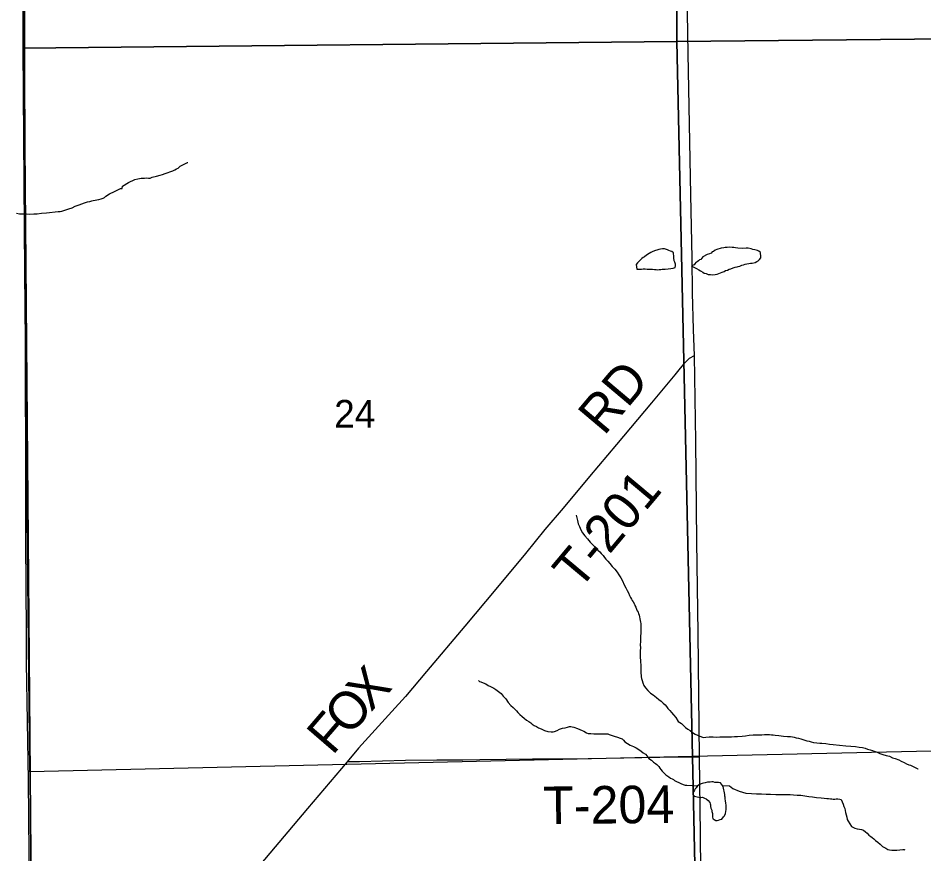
# Model space of a CAD drawing. Extents: x 10.6 to 44.6, y -2.6 to 23.4.
# Drawn here: x 15.273 to 16.643, y 16.432 to 17.696 of the extents above; entities that cross this region are included whole.
import ezdxf

# ---------------------------------------------------------------- set-up
doc = ezdxf.new("R2010")
doc.units = 0
for name, color, linetype in [('GM_X_County_Road', 7, 'Continuous'), ('GM_X_Minor_Lake', 7, 'Continuous'), ('GM_X_Minor_River', 7, 'Continuous'), ('GM_X_Section', 7, 'Continuous'), ('GM_X_Section_Text', 7, 'Continuous'), ('GM_X_Township', 7, 'Continuous'), ('GM_X_Township_Road', 7, 'Continuous'), ('GM_X_Township_Road_Text', 7, 'Continuous')]:
    doc.layers.add(name, color=color, linetype=linetype)

msp = doc.modelspace()

# ---------------------------------------------------------------- linework, layer by layer
at = {"layer": 'GM_X_County_Road'}
msp.add_lwpolyline([(16.2763, 18.1986), (16.2775, 18.1572), (16.2791, 18.0677), (16.2823, 17.8579), (16.286, 17.6424), (16.2902, 17.4286), (16.292, 17.333), (16.2926, 17.2804), (16.2943, 17.2251), (16.2954, 17.1849), (16.2974, 17.0561), (16.299, 16.9044), (16.301, 16.7657), (16.303, 16.5782), (16.3046, 16.4615), (16.3053, 16.4059), (16.3064, 16.3215), (16.308, 16.2088), (16.3086, 16.1439), (16.3111, 15.9738), (16.3131, 15.7931), (16.3156, 15.6219), (16.3166, 15.5267)], dxfattribs=at)
at = {"layer": 'GM_X_Minor_Lake'}
for points in [[(16.2654, 17.3297), (16.2647, 17.3323), (16.2646, 17.335), (16.2646, 17.3369), (16.2642, 17.3388), (16.2641, 17.3407), (16.2618, 17.3429), (16.2599, 17.3436), (16.2572, 17.3447), (16.2553, 17.3454), (16.2507, 17.3469), (16.2476, 17.3472), (16.2446, 17.3467), (16.2419, 17.3459), (16.2389, 17.3451), (16.237, 17.3443), (16.2332, 17.343), (16.2302, 17.3414), (16.2276, 17.3399), (16.2235, 17.3375), (16.2205, 17.3351), (16.2182, 17.3339), (16.2164, 17.3324), (16.2145, 17.3304), (16.2115, 17.3273), (16.2097, 17.3258), (16.2078, 17.3234), (16.2087, 17.3162)], [(16.3965, 17.3352), (16.3966, 17.3369), (16.3962, 17.3395), (16.3958, 17.3414), (16.3934, 17.3433), (16.3915, 17.3444), (16.3892, 17.3451), (16.3873, 17.3454), (16.3846, 17.3461), (16.3816, 17.3468), (16.3773, 17.3478), (16.3743, 17.3478), (16.369, 17.3476), (16.3617, 17.3479), (16.3583, 17.3485), (16.3556, 17.3489), (16.3533, 17.3492), (16.3492, 17.3495), (16.3454, 17.349), (16.3427, 17.349), (16.3404, 17.3485), (16.3366, 17.3481), (16.3298, 17.346), (16.3272, 17.3448), (16.3249, 17.3432), (16.3227, 17.3424), (16.3212, 17.3405), (16.3189, 17.3393), (16.3152, 17.3384), (16.3088, 17.3349), (16.3058, 17.331), (16.3039, 17.3302), (16.3021, 17.329), (16.3002, 17.3271), (16.2983, 17.3263), (16.2965, 17.3243), (16.2954, 17.3228)], [(16.2087, 17.3162), (16.2091, 17.3162), (16.2095, 17.3162), (16.2114, 17.3163), (16.2137, 17.3163), (16.216, 17.3164), (16.2186, 17.3165), (16.2213, 17.3165), (16.2247, 17.3162), (16.227, 17.3163), (16.2293, 17.3163), (16.2327, 17.316), (16.2354, 17.3157), (16.2381, 17.3158), (16.2403, 17.3154), (16.2426, 17.3155), (16.2449, 17.3155), (16.2472, 17.316), (16.2491, 17.316), (16.2517, 17.3161), (16.2563, 17.3165), (16.2605, 17.317), (16.2639, 17.3179), (16.2669, 17.3187), (16.2672, 17.3214), (16.2672, 17.324), (16.2663, 17.3267), (16.2655, 17.3289), (16.2654, 17.3297)], [(16.2954, 17.3228), (16.2916, 17.3212), (16.2931, 17.3204), (16.2962, 17.3186), (16.2989, 17.3171), (16.3024, 17.3153), (16.3054, 17.3139), (16.3085, 17.3116), (16.3109, 17.3102), (16.3139, 17.3095), (16.317, 17.3084), (16.3204, 17.3081), (16.3239, 17.3078), (16.3273, 17.3083), (16.3303, 17.3087), (16.3329, 17.3095), (16.3356, 17.3107), (16.3382, 17.3119), (16.3409, 17.3128), (16.3431, 17.314), (16.3458, 17.3148), (16.3484, 17.316), (16.351, 17.3168), (16.3548, 17.318), (16.3578, 17.3192), (16.3605, 17.3197), (16.3624, 17.3205), (16.3646, 17.3209), (16.3677, 17.3221), (16.3703, 17.3229), (16.373, 17.3238), (16.3809, 17.3255), (16.3832, 17.3255), (16.3877, 17.3264), (16.3904, 17.3276), (16.3922, 17.3288), (16.3945, 17.3307), (16.3963, 17.3334), (16.3965, 17.3352)], [(16.3352, 16.5393), (16.3348, 16.5393), (16.3322, 16.5396), (16.3288, 16.5396), (16.3268, 16.5399), (16.3245, 16.5406), (16.3223, 16.5409), (16.32, 16.5405), (16.3177, 16.5405), (16.3158, 16.5404), (16.3124, 16.5392), (16.3097, 16.5388), (16.3079, 16.5383), (16.306, 16.5379), (16.3033, 16.5363), (16.3007, 16.5347), (16.2985, 16.532), (16.297, 16.5301), (16.2959, 16.5282), (16.2945, 16.5255), (16.2941, 16.5236), (16.2942, 16.5213), (16.2961, 16.519), (16.2999, 16.518), (16.3026, 16.5177), (16.3057, 16.5173), (16.3083, 16.5174), (16.3114, 16.5163), (16.3137, 16.5149), (16.3168, 16.5127), (16.3195, 16.5097), (16.32, 16.5078), (16.3204, 16.5059)], [(16.3352, 16.5393), (16.3348, 16.5393), (16.3322, 16.5396), (16.3288, 16.5396), (16.3268, 16.5399), (16.3245, 16.5406), (16.3223, 16.5409), (16.32, 16.5405), (16.3177, 16.5405), (16.3158, 16.5404), (16.3124, 16.5392), (16.3097, 16.5388), (16.3079, 16.5383), (16.306, 16.5379), (16.3033, 16.5363), (16.3007, 16.5347), (16.2985, 16.532), (16.297, 16.5301), (16.2959, 16.5282), (16.2945, 16.5255), (16.2941, 16.5236), (16.2942, 16.5213), (16.2961, 16.519), (16.2999, 16.518), (16.3026, 16.5177), (16.3057, 16.5173), (16.3083, 16.5174), (16.3114, 16.5163), (16.3137, 16.5149), (16.3168, 16.5127), (16.3195, 16.5097), (16.32, 16.5078), (16.3204, 16.5059), (16.3204, 16.5036), (16.3209, 16.501), (16.3221, 16.4979), (16.3221, 16.496), (16.3233, 16.493), (16.3234, 16.4907), (16.3235, 16.4881), (16.3239, 16.485), (16.3258, 16.4839), (16.3285, 16.4825), (16.3304, 16.4825), (16.3323, 16.4829), (16.335, 16.4838), (16.3372, 16.4842), (16.3398, 16.4877), (16.3417, 16.4896), (16.3428, 16.4931), (16.3434, 16.4961), (16.3438, 16.4988), (16.3441, 16.5019), (16.344, 16.5057), (16.3435, 16.5087), (16.3431, 16.5121), (16.3426, 16.5151), (16.3426, 16.5174), (16.3422, 16.5193), (16.3421, 16.5216), (16.3413, 16.5242), (16.3408, 16.5269), (16.3404, 16.5288), (16.3395, 16.5337), (16.3384, 16.5352), (16.3352, 16.5393)], [(16.3204, 16.5059), (16.3204, 16.5036), (16.3209, 16.501), (16.3221, 16.4979), (16.3221, 16.496), (16.3233, 16.493), (16.3234, 16.4907), (16.3235, 16.4881), (16.3239, 16.485), (16.3258, 16.4839), (16.3285, 16.4825), (16.3304, 16.4825), (16.3323, 16.4829), (16.335, 16.4838), (16.3372, 16.4842), (16.3398, 16.4877), (16.3417, 16.4896), (16.3428, 16.4931), (16.3434, 16.4961), (16.3438, 16.4988), (16.3441, 16.5019), (16.344, 16.5057), (16.3435, 16.5087), (16.3431, 16.5121), (16.3426, 16.5151), (16.3426, 16.5174), (16.3422, 16.5193), (16.3421, 16.5216), (16.3413, 16.5242), (16.3408, 16.5269), (16.3404, 16.5288), (16.3395, 16.5337), (16.3384, 16.5352), (16.3352, 16.5393)]]:
    msp.add_lwpolyline(points, dxfattribs=at)
at = {"layer": 'GM_X_Minor_River'}
for points in [[(15.495, 17.4607), (15.5067, 17.4648), (15.5097, 17.4667), (15.5124, 17.4679), (15.5146, 17.4691), (15.5176, 17.4719), (15.5217, 17.4742), (15.5251, 17.4754), (15.527, 17.4766), (15.5289, 17.4778), (15.5296, 17.4778)], [(15.2703, 17.4007), (15.2745, 17.4), (15.2772, 17.4001), (15.2799, 17.3998), (15.2852, 17.3999), (15.2905, 17.3996), (15.2962, 17.3997), (15.3015, 17.3999), (15.308, 17.4008), (15.3156, 17.4013), (15.3334, 17.4032), (15.3361, 17.4037), (15.3387, 17.4041), (15.3418, 17.4049), (15.3448, 17.4061), (15.3493, 17.4074), (15.3542, 17.409), (15.3591, 17.4114), (15.3648, 17.4134), (15.3689, 17.415), (15.3731, 17.4166), (15.3776, 17.4179), (15.381, 17.4187), (15.384, 17.4195), (15.3863, 17.42), (15.3894, 17.4204), (15.392, 17.4212), (15.3947, 17.4217), (15.3981, 17.4225), (15.4015, 17.4237), (15.4033, 17.4245), (15.4056, 17.4265), (15.4108, 17.4304), (15.4184, 17.4336), (15.4236, 17.4364), (15.4278, 17.438), (15.4301, 17.4384), (15.4304, 17.4418), (15.4398, 17.4474), (15.4492, 17.4521), (15.4537, 17.453), (15.4586, 17.4538), (15.464, 17.454), (15.467, 17.4544), (15.47, 17.4541), (15.4723, 17.4541), (15.4757, 17.4554), (15.4822, 17.457), (15.4875, 17.4583), (15.4912, 17.4595), (15.495, 17.4607)], [(16.1168, 16.9444), (16.1189, 16.9359), (16.1201, 16.931), (16.1221, 16.9269), (16.1242, 16.922), (16.1265, 16.9175), (16.1301, 16.913), (16.134, 16.9085), (16.1383, 16.9033), (16.143, 16.8988), (16.1468, 16.8947), (16.15, 16.8914), (16.1527, 16.8888), (16.155, 16.8862), (16.1578, 16.8832), (16.1597, 16.8802), (16.1621, 16.8776), (16.1648, 16.8746), (16.1679, 16.8709), (16.1715, 16.8667), (16.1754, 16.8623), (16.1789, 16.8582), (16.1816, 16.854), (16.1844, 16.8495), (16.1872, 16.845), (16.1896, 16.839), (16.1924, 16.8341), (16.1944, 16.8304), (16.196, 16.8266), (16.1976, 16.8228), (16.1995, 16.8198), (16.2008, 16.8172), (16.2019, 16.8149), (16.2031, 16.8131), (16.2051, 16.8097), (16.2059, 16.8074), (16.2075, 16.8048), (16.2083, 16.8021), (16.2095, 16.7995), (16.2107, 16.7976), (16.2115, 16.7954), (16.2123, 16.7927), (16.2128, 16.7904), (16.2136, 16.7874), (16.214, 16.7851), (16.2145, 16.7825), (16.2149, 16.7802), (16.215, 16.7776), (16.215, 16.7749), (16.2149, 16.765), (16.2146, 16.7616), (16.2143, 16.7578), (16.2144, 16.7532), (16.2141, 16.7482), (16.2142, 16.7437), (16.2139, 16.7391), (16.214, 16.7349), (16.2137, 16.7326), (16.2138, 16.7307), (16.2138, 16.7284), (16.2143, 16.725), (16.2144, 16.7212), (16.2148, 16.7182), (16.2149, 16.7159), (16.2149, 16.7132), (16.215, 16.7113), (16.215, 16.7079), (16.2151, 16.7049), (16.2152, 16.7022), (16.2156, 16.6996), (16.216, 16.6973), (16.2169, 16.6939), (16.2181, 16.6905), (16.2193, 16.6867), (16.2221, 16.683), (16.2256, 16.6789), (16.2295, 16.6751), (16.2334, 16.6722), (16.2384, 16.6685), (16.2419, 16.6655), (16.2458, 16.6626), (16.2489, 16.66), (16.2516, 16.6574), (16.2535, 16.6548), (16.2559, 16.6518), (16.2586, 16.6488), (16.2614, 16.6458), (16.2641, 16.6421), (16.2676, 16.638), (16.2712, 16.6323), (16.2762, 16.629), (16.2793, 16.626), (16.2824, 16.6231), (16.2859, 16.6205), (16.2894, 16.6183), (16.2933, 16.6153), (16.2971, 16.6131), (16.3006, 16.6113)], [(15.9692, 16.6939), (15.9707, 16.6925), (15.973, 16.6921), (15.9761, 16.6907), (15.9803, 16.6889), (15.9838, 16.6867), (15.9873, 16.6852), (15.9904, 16.6834), (15.9927, 16.6823), (15.9954, 16.6805), (16.0035, 16.6742), (16.0066, 16.6704), (16.0105, 16.6663), (16.0141, 16.6607), (16.0184, 16.6563), (16.0219, 16.6533), (16.0238, 16.651), (16.0269, 16.6481), (16.0289, 16.6455), (16.0316, 16.6429), (16.0351, 16.6399), (16.0386, 16.6369), (16.0417, 16.634), (16.0452, 16.6321), (16.0486, 16.6299), (16.0506, 16.6281), (16.0537, 16.6262), (16.0568, 16.6244), (16.0599, 16.6226), (16.0641, 16.6208), (16.0691, 16.6186), (16.0744, 16.6172), (16.0794, 16.6165), (16.0824, 16.6166), (16.0843, 16.617), (16.0881, 16.6186), (16.0919, 16.6203), (16.0964, 16.6219), (16.1006, 16.6227), (16.104, 16.6236), (16.107, 16.6244), (16.1089, 16.6245), (16.1108, 16.6241), (16.1135, 16.6234), (16.1189, 16.6213), (16.1227, 16.6198), (16.1262, 16.6184), (16.1288, 16.6173), (16.1327, 16.6151), (16.1354, 16.614), (16.1392, 16.6137), (16.1438, 16.6134), (16.1483, 16.6136), (16.1537, 16.6133), (16.1582, 16.6134), (16.1651, 16.6132), (16.167, 16.6125), (16.1701, 16.6114), (16.1747, 16.61), (16.1797, 16.6082), (16.1835, 16.6067), (16.1866, 16.6061), (16.1889, 16.6038), (16.1909, 16.6012), (16.1947, 16.5986), (16.1989, 16.5964), (16.2036, 16.5943), (16.2078, 16.5921), (16.212, 16.5899), (16.2155, 16.5873), (16.2186, 16.5847), (16.2217, 16.5825), (16.2244, 16.5795), (16.2272, 16.5762), (16.2311, 16.5736), (16.2342, 16.5706), (16.2369, 16.5688), (16.2392, 16.5669), (16.2419, 16.5639), (16.2435, 16.5617), (16.2451, 16.5594), (16.2474, 16.5568), (16.2501, 16.5538), (16.2529, 16.5512), (16.2571, 16.5483), (16.2598, 16.5465), (16.2621, 16.5454), (16.2641, 16.5443), (16.266, 16.5428), (16.2687, 16.5413), (16.2722, 16.5399), (16.2756, 16.5384), (16.2791, 16.537), (16.2821, 16.5359), (16.2844, 16.5356), (16.3007, 16.5347)], [(16.3006, 16.6113), (16.309, 16.6081), (16.3132, 16.6082), (16.3181, 16.6087), (16.3242, 16.6088), (16.3299, 16.6086), (16.3345, 16.6087), (16.3372, 16.6087), (16.3402, 16.6088), (16.3433, 16.6089), (16.3474, 16.609), (16.352, 16.6091), (16.3566, 16.6095), (16.3611, 16.6096), (16.368, 16.6098), (16.3733, 16.6103), (16.379, 16.6112), (16.3847, 16.6117), (16.3892, 16.6118), (16.3934, 16.6119), (16.398, 16.612), (16.4021, 16.6125), (16.4063, 16.6126), (16.4094, 16.6123), (16.4124, 16.612), (16.4151, 16.612), (16.4182, 16.6113), (16.4239, 16.6107), (16.4307, 16.6101), (16.4368, 16.6095), (16.4414, 16.6092), (16.4445, 16.6089), (16.4468, 16.6082), (16.4498, 16.6075), (16.4536, 16.6068), (16.4571, 16.6057), (16.4602, 16.6047), (16.4632, 16.604), (16.4663, 16.6029), (16.4694, 16.6022), (16.4728, 16.6012), (16.4762, 16.6005), (16.4812, 16.5998), (16.4858, 16.5995), (16.4888, 16.5992), (16.4949, 16.5986), (16.5003, 16.598), (16.506, 16.5973), (16.5251, 16.5951), (16.5327, 16.5949), (16.5395, 16.5943), (16.5453, 16.5933), (16.5502, 16.5926), (16.5544, 16.5916), (16.5579, 16.5901), (16.5621, 16.5891), (16.5652, 16.588), (16.5682, 16.5873), (16.5709, 16.5863), (16.5736, 16.5852), (16.5767, 16.5837), (16.5813, 16.5823), (16.5863, 16.5809), (16.5913, 16.5795), (16.5959, 16.5773), (16.5997, 16.5759), (16.6051, 16.5741), (16.6089, 16.5719), (16.6132, 16.5701), (16.617, 16.5683), (16.6205, 16.5668), (16.6231, 16.5658), (16.6262, 16.5643), (16.6289, 16.5628), (16.6312, 16.5618), (16.6339, 16.5603), (16.6343, 16.5603)], [(16.3384, 16.5352), (16.3491, 16.5348), (16.3542, 16.5307), (16.3638, 16.5268), (16.3737, 16.5239), (16.3825, 16.523), (16.3901, 16.5228), (16.3977, 16.5226), (16.4046, 16.5224), (16.4111, 16.5221), (16.4194, 16.5216), (16.4248, 16.5217), (16.4301, 16.5218), (16.435, 16.5219), (16.4408, 16.5217), (16.4461, 16.5214), (16.4514, 16.5208), (16.4571, 16.5205), (16.4632, 16.5199), (16.469, 16.5189), (16.4747, 16.5182), (16.4808, 16.5169), (16.488, 16.5166), (16.4922, 16.516), (16.4961, 16.5157), (16.4991, 16.5154), (16.5018, 16.5151), (16.5041, 16.5151), (16.506, 16.5148), (16.5083, 16.5148), (16.5105, 16.5149), (16.5132, 16.5149), (16.5159, 16.5146), (16.5182, 16.5143), (16.5194, 16.5105), (16.521, 16.5071), (16.5222, 16.5037), (16.5234, 16.5007), (16.5239, 16.4973), (16.5247, 16.4943), (16.5255, 16.4909), (16.5264, 16.4875), (16.5272, 16.484), (16.5288, 16.4814), (16.5339, 16.4735), (16.5366, 16.4717), (16.5389, 16.4706), (16.5424, 16.4696), (16.5458, 16.4692), (16.5489, 16.4686), (16.5519, 16.4679), (16.555, 16.4653), (16.5574, 16.463), (16.5601, 16.4604), (16.5628, 16.4582), (16.5651, 16.4564), (16.5675, 16.4545), (16.5702, 16.4523), (16.5733, 16.4497), (16.5772, 16.4467), (16.5807, 16.443), (16.5857, 16.4405), (16.5888, 16.4386), (16.5914, 16.4379), (16.5945, 16.4376), (16.5975, 16.4373), (16.6021, 16.4374), (16.6067, 16.4379), (16.6112, 16.4384), (16.6135, 16.4384), (16.6146, 16.4381), (16.6146, 16.4385)]]:
    msp.add_lwpolyline(points, dxfattribs=at)
at = {"layer": 'GM_X_Section'}
for points in [[(15.2751, 18.7912), (16.2657, 18.7944), (16.2696, 17.6606), (15.2802, 17.6505)], [(16.2657, 18.7944), (17.2198, 18.8008), (17.2448, 17.6704), (16.2696, 17.6606)], [(17.2448, 17.6704), (17.2647, 16.6007), (16.2932, 16.5791), (16.2696, 17.6606)], [(16.2696, 17.6606), (16.2932, 16.5791), (15.2902, 16.5559), (15.2897, 16.6058), (15.2863, 16.9412), (15.2826, 17.3124), (15.2802, 17.6505)]]:
    msp.add_lwpolyline(points, close=True, dxfattribs=at)
for points in [[(17.2881, 15.5267), (17.2647, 16.6007), (16.2932, 16.5791), (16.3159, 15.5267)], [(16.3159, 15.5267), (16.2932, 16.5791), (15.2902, 16.5559), (15.2932, 16.204), (15.2963, 15.8392), (15.2987, 15.5267)]]:
    msp.add_lwpolyline(points, dxfattribs=at)
at = {"layer": 'GM_X_Township'}
for points in [[(15.2903, 15.5267), (15.2954, 16.015), (15.2788, 17.979), (15.2737, 18.9996)], [(15.2737, 18.9996), (15.2788, 17.979), (15.2954, 16.015), (15.2903, 15.5267)]]:
    msp.add_lwpolyline(points, dxfattribs=at)
at = {"layer": 'GM_X_Township_Road'}
for points in [[(15.2837, 17.2802), (15.2834, 17.4331), (15.2825, 17.935), (15.282, 17.9525), (15.28, 17.9719), (15.2788, 17.9838), (15.2786, 17.9856)], [(15.2973, 16.0158), (15.2953, 16.0211), (15.2943, 16.0277), (15.2926, 16.1765), (15.291, 16.2829), (15.2894, 16.3563), (15.2892, 16.4328), (15.2883, 16.5432), (15.2854, 16.7208), (15.2851, 16.7668), (15.2845, 16.905), (15.2837, 17.2802)], [(16.2954, 17.1849), (16.288, 17.1809), (16.2837, 17.1768), (16.2795, 17.1724), (16.2725, 17.1638), (16.2664, 17.1564), (16.231, 17.1142), (16.1782, 17.0512), (16.1372, 17.0024), (16.0974, 16.9546), (16.0696, 16.9223), (16.0402, 16.8864), (15.9957, 16.8323), (15.9488, 16.7764), (15.8905, 16.7075), (15.8586, 16.67), (15.8382, 16.6474), (15.7878, 16.5918), (15.7706, 16.5713), (15.7105, 16.5004), (15.6319, 16.4072)], [(16.303, 16.5782), (16.2438, 16.5778), (16.108, 16.5753), (16.0511, 16.5749), (15.9711, 16.574), (15.9455, 16.5737), (15.906, 16.5737), (15.8588, 16.5729), (15.789, 16.5711), (15.7706, 16.5713)]]:
    msp.add_lwpolyline(points, dxfattribs=at)

# ---------------------------------------------------------------- texts
at = {"layer": 'GM_X_Section_Text'}
msp.add_text('24', height=0.04186, rotation=0, dxfattribs=at).set_placement((15.7509, 17.0766))
at = {"layer": 'GM_X_Township_Road_Text'}
for s, height, rotation, p in [('RD', 0.05682, 49.8806, (16.1593, 17.0631)), ('T-201', 0.05682, 50.0897, (16.1212, 16.8289)), ('X', 0.0568, 47.605, (15.8065, 16.6455)), ('O', 0.0568, 47.9223, (15.7731, 16.6085)), ('F', 0.0568, 49.2642, (15.7483, 16.5797)), ('T-204', 0.05682, 0.561, (16.0673, 16.4768))]:
    msp.add_text(s, height=height, rotation=rotation, dxfattribs=at).set_placement(p)

doc.saveas('drawing.dxf')
